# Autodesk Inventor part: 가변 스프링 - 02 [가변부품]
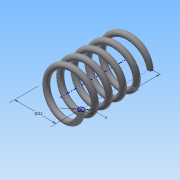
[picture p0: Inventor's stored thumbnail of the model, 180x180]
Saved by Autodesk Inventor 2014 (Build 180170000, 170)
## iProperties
Created: 2015-09
Part Number: 가변 스프링 - 02 [가변부품]
Material: 강철, 탄소
Document SubType Name: Modeling
Designer: study
Density: 1 g/cm^3
Appearance: 반연마
Author: study
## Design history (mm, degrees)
sketch "스케치1"
  geometry: L1 (0, 0)-(11, 0); L2 (11, 0)-(11, 29.193); L3 (11, 29.193)-(0, 29.193); L4 (0, 29.193)-(0, 0); C1 r 1.5 at (11, 0)
  constraints: 8 end point, 2 parallel, 1 centre point, 1 coincident, 1 horizontal, 1 perpendicular
  dimensions: "d0" = 22 diameter of L2 L4; "d1" = 29.19259 distance between parallel lines of L3 L1 (derived); "d2" = 3 diameter of C1
feature "코일1" sketch "스케치1" pitch "d3" = 10; turns "d5" = 5; dims "d4" = 29.19259 (= d1), "d6" = 0, angle "d7" = 90 deg, angle "d8" = 90 deg, "d9" = 0, "d10" = 0
node "작업 평면1"
sketch "스케치2"
  geometry: L1 (-12.5, 0)-(-9.5, 0) reference; L2 (-12.5, 0)-(-9.5, 0) reference; 1 further point
  constraints: 2 horizontal alignment
extrude "돌출1" cut sketch "스케치2" stored distance "d12" = 10; taper "d13" = 0 deg
node "작업 평면2"
sketch "스케치3"
  geometry: L1 (-9.5, 0)-(-12.5, 0) reference; 1 further point
  constraints: 1 horizontal alignment
extrude "돌출2" cut sketch "스케치3" stored distance "d15" = 10; taper "d16" = 0 deg
node "솔리드1"
node "절단 모서리 투영1"
node "절단 모서리 투영2"
node "절단 모서리 투영3"
other parameters: "d11" = 0, "d14" = 29.19259 (= d1)
